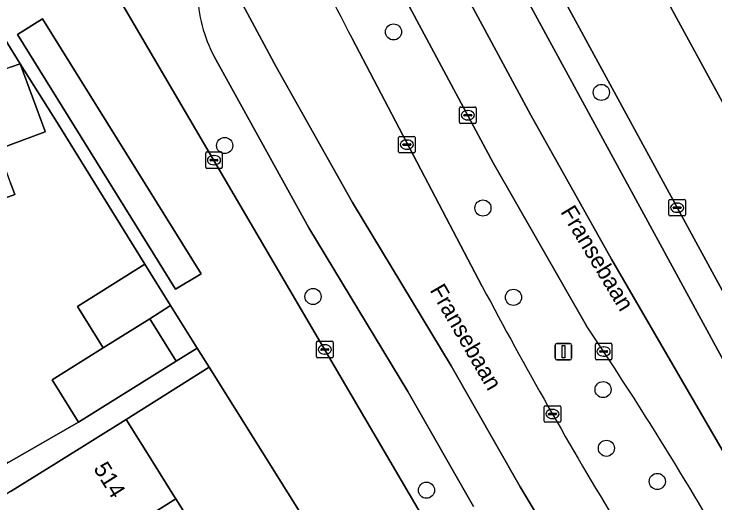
# Model space of a CAD drawing. Extents: x 157767 to 159172, y 387839 to 389425.
# Drawn here: x 158500.2 to 158542.71, y 388310.69 to 388340.3 of the extents above; entities that cross this region are included whole.
import ezdxf

# ---------------------------------------------------------------- set-up
doc = ezdxf.new("R2010")
doc.units = 0
for name, color, linetype in [('IMGEO_Berm_groen', 7, 'Continuous'), ('IMGEO_Boom', 7, 'Continuous'), ('IMGEO_Erf', 7, 'Continuous'), ('IMGEO_Kolk', 7, 'Continuous'), ('IMGEO_Lichtmast', 7, 'Continuous'), ('IMGEO_Muur', 7, 'Continuous'), ('IMGEO_Openbare_ruimte_label', 7, 'Continuous'), ('IMGEO_Pand', 7, 'Continuous'), ('IMGEO_Pand_nummerreeks', 7, 'Continuous'), ('IMGEO_Parkeervlak_open', 7, 'Continuous'), ('IMGEO_Rijbaan_lokaal_gesloten', 7, 'Continuous'), ('IMGEO_Rijbaan_lokaal_open', 7, 'Continuous'), ('IMGEO_Verkeerseiland_open', 7, 'Continuous'), ('IMGEO_Voetpad_open', 7, 'Continuous')]:
    doc.layers.add(name, color=color, linetype=linetype)

msp = doc.modelspace()

# ---------------------------------------------------------------- linework, layer by layer
at = {"layer": 'IMGEO_Berm_groen'}
for points in [[(158529.258, 388331.294), (158524.031, 388341.037)], [(158520.698, 388338.819), (158528.598, 388323.799)], [(158534.917, 388321.411), (158529.258, 388331.294)]]:
    msp.add_lwpolyline(points, dxfattribs=at)
for centre, radius, start, end in [((158763.078, 388464.134), 272.859, 203.9844, 207.33977), ((158776.555, 388455.267), 280.654, 207.9327, 211.32432), ((158344.877, 388193.312), 229.182, 30.48594, 33.98258)]:
    msp.add_arc(centre, radius, start, end, dxfattribs=at)
at = {"layer": 'IMGEO_Boom'}
for centre in [(158523.215, 388339.218), (158535.816, 388335.554), (158512.977, 388332.335), (158528.635, 388328.551), (158518.336, 388323.19), (158530.487, 388323.141), (158535.921, 388317.554), (158536.123, 388313.998), (158539.208, 388311.991), (158525.212, 388311.457)]:
    msp.add_circle(centre, 0.489, dxfattribs=at)
at = {"layer": 'IMGEO_Erf'}
for points in [[(158477.052, 388309.252), (158478.936, 388310.46), (158481.128, 388307.041), (158480.913, 388306.903), (158483.29, 388302.771), (158483.534, 388302.924), (158482.117, 388305.189), (158485.665, 388307.409), (158489.217, 388309.632), (158490.635, 388307.366), (158492.742, 388308.684), (158491.323, 388310.952), (158495, 388313.253), (158498.378, 388315.367), (158499.798, 388313.098), (158504.118, 388315.572), (158502.511, 388318.15), (158505.612, 388320.092), (158504.046, 388322.595), (158508.134, 388325.154), (158502.814, 388333.732), (158500.583, 388337.29), (158500, 388338.235), (158496.17, 388344.444)], [(158500, 388337.076), (158500.583, 388337.29), (158502.065, 388333.257), (158502.098, 388333.166), (158499.238, 388332.119)], [(158500, 388330.073), (158500.244, 388329.371), (158495.536, 388327.648)]]:
    msp.add_lwpolyline(points, dxfattribs=at)
for points in [[(158509.684, 388322.644), (158508.434, 388321.842), (158510.045, 388319.266), (158511.308, 388320.053)], [(158512.028, 388318.905), (158506.997, 388315.751), (158508.597, 388313.194), (158509.89, 388311.127), (158510.015, 388310.928), (158512.878, 388306.351), (158515.743, 388301.774), (158518.606, 388297.197), (158521.472, 388292.617), (158524.478, 388287.813), (158529.553, 388290.95)]]:
    msp.add_lwpolyline(points, close=True, dxfattribs=at)
at = {"layer": 'IMGEO_Kolk'}
for p, q in [((158527.292, 388334.67), (158528.144, 388334.67)), ((158527.217, 388333.744), (158527.217, 388334.596)), ((158527.519, 388334.213), (158527.917, 388334.213)), ((158527.705, 388334.45), (158527.73, 388334.45)), ((158528.218, 388334.596), (158528.218, 388333.744)), ((158527.476, 388334.164), (158527.476, 388334.176)), ((158527.914, 388334.127), (158527.516, 388334.127)), ((158527.728, 388333.89), (158527.703, 388333.89)), ((158527.96, 388334.176), (158527.96, 388334.164)), ((158528.144, 388333.67), (158527.292, 388333.67)), ((158523.526, 388331.964), (158523.526, 388332.816)), ((158523.601, 388332.89), (158524.453, 388332.89)), ((158524.014, 388332.67), (158524.039, 388332.67)), ((158524.527, 388332.816), (158524.527, 388331.964)), ((158523.785, 388332.384), (158523.785, 388332.396)), ((158524.223, 388332.347), (158523.825, 388332.347)), ((158523.828, 388332.433), (158524.226, 388332.433)), ((158524.037, 388332.11), (158524.012, 388332.11)), ((158524.269, 388332.396), (158524.269, 388332.384)), ((158511.826, 388331.025), (158511.826, 388331.877)), ((158511.901, 388331.951), (158512.753, 388331.951)), ((158512.314, 388331.731), (158512.339, 388331.731)), ((158512.827, 388331.877), (158512.827, 388331.025)), ((158524.453, 388331.89), (158523.601, 388331.89)), ((158512.085, 388331.445), (158512.085, 388331.457)), ((158512.523, 388331.408), (158512.125, 388331.408)), ((158512.128, 388331.494), (158512.526, 388331.494)), ((158512.569, 388331.457), (158512.569, 388331.445)), ((158512.753, 388330.951), (158511.901, 388330.951)), ((158512.337, 388331.171), (158512.312, 388331.171)), ((158539.913, 388328.145), (158539.913, 388328.997)), ((158539.988, 388329.071), (158540.84, 388329.071)), ((158540.401, 388328.851), (158540.426, 388328.851)), ((158540.914, 388328.997), (158540.914, 388328.145)), ((158540.172, 388328.565), (158540.172, 388328.577)), ((158540.61, 388328.528), (158540.212, 388328.528)), ((158540.215, 388328.614), (158540.613, 388328.614)), ((158540.424, 388328.291), (158540.399, 388328.291)), ((158540.656, 388328.577), (158540.656, 388328.565)), ((158540.84, 388328.071), (158539.988, 388328.071)), ((158518.546, 388319.559), (158518.546, 388320.411)), ((158518.621, 388320.485), (158519.473, 388320.485)), ((158519.034, 388320.265), (158519.059, 388320.265)), ((158519.547, 388320.411), (158519.547, 388319.559)), ((158535.452, 388319.432), (158535.452, 388320.284)), ((158535.527, 388320.358), (158536.379, 388320.358)), ((158536.453, 388320.284), (158536.453, 388319.432)), ((158518.805, 388319.979), (158518.805, 388319.991)), ((158519.243, 388319.942), (158518.845, 388319.942)), ((158518.848, 388320.028), (158519.246, 388320.028)), ((158519.289, 388319.991), (158519.289, 388319.979)), ((158535.711, 388319.852), (158535.711, 388319.864)), ((158536.149, 388319.815), (158535.751, 388319.815)), ((158535.754, 388319.901), (158536.152, 388319.901)), ((158535.94, 388320.138), (158535.965, 388320.138)), ((158536.195, 388319.864), (158536.195, 388319.852)), ((158519.473, 388319.485), (158518.621, 388319.485)), ((158519.057, 388319.705), (158519.032, 388319.705)), ((158536.379, 388319.358), (158535.527, 388319.358)), ((158535.963, 388319.578), (158535.938, 388319.578)), ((158532.35, 388315.65), (158532.35, 388316.502)), ((158532.425, 388316.576), (158533.277, 388316.576)), ((158532.838, 388316.356), (158532.863, 388316.356)), ((158533.351, 388316.502), (158533.351, 388315.65)), ((158532.609, 388316.07), (158532.609, 388316.082)), ((158533.047, 388316.033), (158532.649, 388316.033)), ((158532.652, 388316.119), (158533.05, 388316.119)), ((158533.093, 388316.082), (158533.093, 388316.07)), ((158533.277, 388315.576), (158532.425, 388315.576)), ((158532.861, 388315.796), (158532.836, 388315.796))]:
    msp.add_line(p, q, dxfattribs=at)
for points in [[(158527.292, 388334.67), (158528.144, 388334.67)], [(158527.217, 388333.744), (158527.217, 388334.596)], [(158528.218, 388334.596), (158528.218, 388333.744)], [(158528.144, 388333.67), (158527.292, 388333.67)], [(158523.526, 388331.964), (158523.526, 388332.816)], [(158523.601, 388332.89), (158524.453, 388332.89)], [(158524.527, 388332.816), (158524.527, 388331.964)], [(158511.826, 388331.025), (158511.826, 388331.877)], [(158511.901, 388331.951), (158512.753, 388331.951)], [(158512.827, 388331.877), (158512.827, 388331.025)], [(158524.453, 388331.89), (158523.601, 388331.89)], [(158512.753, 388330.951), (158511.901, 388330.951)], [(158539.913, 388328.145), (158539.913, 388328.997)], [(158539.988, 388329.071), (158540.84, 388329.071)], [(158540.914, 388328.997), (158540.914, 388328.145)], [(158540.84, 388328.071), (158539.988, 388328.071)], [(158518.546, 388319.559), (158518.546, 388320.411)], [(158518.621, 388320.485), (158519.473, 388320.485)], [(158519.547, 388320.411), (158519.547, 388319.559)], [(158535.452, 388319.432), (158535.452, 388320.284)], [(158535.527, 388320.358), (158536.379, 388320.358)], [(158536.453, 388320.284), (158536.453, 388319.432)], [(158519.473, 388319.485), (158518.621, 388319.485)], [(158536.379, 388319.358), (158535.527, 388319.358)], [(158532.35, 388315.65), (158532.35, 388316.502)], [(158532.425, 388316.576), (158533.277, 388316.576)], [(158533.351, 388316.502), (158533.351, 388315.65)], [(158533.277, 388315.576), (158532.425, 388315.576)]]:
    msp.add_lwpolyline(points, dxfattribs=at)
for centre, radius, start, end in [((158527.294, 388334.594), 0.0765, 91.552, 178.448), ((158527.294, 388334.594), 0.0765, 91.552, 178.448), ((158528.142, 388334.594), 0.0765, 1.552, 88.448), ((158528.142, 388334.594), 0.0765, 1.552, 88.448), ((158527.516, 388334.173), 0.0403, 85.8775, 175.7526), ((158527.921, 388334.175), 0.0386, 1.7309, 96.639), ((158527.513, 388334.163), 0.0366, 178.938, 274.7102), ((158527.917, 388334.17), 0.043, 264.8664, 352.4533), ((158527.294, 388333.746), 0.0765, 181.552, 268.448), ((158527.294, 388333.746), 0.0765, 181.552, 268.448), ((158528.142, 388333.746), 0.0765, 271.552, 358.448), ((158528.142, 388333.746), 0.0765, 271.552, 358.448), ((158523.603, 388332.814), 0.0765, 91.552, 178.448), ((158523.603, 388332.814), 0.0765, 91.552, 178.448), ((158524.451, 388332.814), 0.0765, 1.552, 88.448), ((158524.451, 388332.814), 0.0765, 1.552, 88.448), ((158523.825, 388332.393), 0.0403, 85.8775, 175.7526), ((158523.822, 388332.383), 0.0366, 178.938, 274.7102), ((158524.226, 388332.39), 0.043, 264.8664, 352.4533), ((158524.23, 388332.395), 0.0386, 1.7309, 96.639), ((158511.903, 388331.875), 0.0765, 91.552, 178.448), ((158511.903, 388331.875), 0.0765, 91.552, 178.448), ((158512.751, 388331.875), 0.0765, 1.552, 88.448), ((158512.751, 388331.875), 0.0765, 1.552, 88.448), ((158523.603, 388331.966), 0.0765, 181.552, 268.448), ((158523.603, 388331.966), 0.0765, 181.552, 268.448), ((158524.451, 388331.966), 0.0765, 271.552, 358.448), ((158524.451, 388331.966), 0.0765, 271.552, 358.448), ((158512.125, 388331.454), 0.0403, 85.8775, 175.7526), ((158512.122, 388331.444), 0.0366, 178.938, 274.7102), ((158512.526, 388331.451), 0.043, 264.8664, 352.4533), ((158512.53, 388331.456), 0.0386, 1.7309, 96.639), ((158511.903, 388331.027), 0.0765, 181.552, 268.448), ((158511.903, 388331.027), 0.0765, 181.552, 268.448), ((158512.751, 388331.027), 0.0765, 271.552, 358.448), ((158512.751, 388331.027), 0.0765, 271.552, 358.448), ((158539.99, 388328.995), 0.0765, 91.552, 178.448), ((158539.99, 388328.995), 0.0765, 91.552, 178.448), ((158540.838, 388328.995), 0.0765, 1.552, 88.448), ((158540.838, 388328.995), 0.0765, 1.552, 88.448), ((158540.212, 388328.574), 0.0403, 85.8775, 175.7526), ((158540.209, 388328.564), 0.0366, 178.938, 274.7102), ((158540.613, 388328.571), 0.043, 264.8664, 352.4533), ((158540.617, 388328.576), 0.0386, 1.7309, 96.639), ((158539.99, 388328.147), 0.0765, 181.552, 268.448), ((158539.99, 388328.147), 0.0765, 181.552, 268.448), ((158540.838, 388328.147), 0.0765, 271.552, 358.448), ((158540.838, 388328.147), 0.0765, 271.552, 358.448), ((158518.623, 388320.409), 0.0765, 91.552, 178.448), ((158518.623, 388320.409), 0.0765, 91.552, 178.448), ((158519.471, 388320.409), 0.0765, 1.552, 88.448), ((158519.471, 388320.409), 0.0765, 1.552, 88.448), ((158535.529, 388320.282), 0.0765, 91.552, 178.448), ((158535.529, 388320.282), 0.0765, 91.552, 178.448), ((158536.377, 388320.282), 0.0765, 1.552, 88.448), ((158536.377, 388320.282), 0.0765, 1.552, 88.448), ((158518.845, 388319.988), 0.0403, 85.8775, 175.7526), ((158518.842, 388319.978), 0.0366, 178.938, 274.7102), ((158519.246, 388319.985), 0.043, 264.8664, 352.4533), ((158519.25, 388319.99), 0.0386, 1.7309, 96.639), ((158535.751, 388319.861), 0.0403, 85.8775, 175.7526), ((158535.748, 388319.851), 0.0366, 178.938, 274.7102), ((158536.152, 388319.858), 0.043, 264.8664, 352.4533), ((158536.156, 388319.863), 0.0386, 1.7309, 96.639), ((158518.623, 388319.561), 0.0765, 181.552, 268.448), ((158518.623, 388319.561), 0.0765, 181.552, 268.448), ((158519.471, 388319.561), 0.0765, 271.552, 358.448), ((158519.471, 388319.561), 0.0765, 271.552, 358.448), ((158535.529, 388319.434), 0.0765, 181.552, 268.448), ((158535.529, 388319.434), 0.0765, 181.552, 268.448), ((158536.377, 388319.434), 0.0765, 271.552, 358.448), ((158536.377, 388319.434), 0.0765, 271.552, 358.448), ((158532.427, 388316.5), 0.0765, 91.552, 178.448), ((158532.427, 388316.5), 0.0765, 91.552, 178.448), ((158533.275, 388316.5), 0.0765, 1.552, 88.448), ((158533.275, 388316.5), 0.0765, 1.552, 88.448), ((158532.649, 388316.079), 0.0403, 85.8775, 175.7526), ((158532.646, 388316.069), 0.0366, 178.938, 274.7102), ((158533.05, 388316.076), 0.043, 264.8664, 352.4533), ((158533.054, 388316.081), 0.0386, 1.7309, 96.639), ((158532.427, 388315.652), 0.0765, 181.552, 268.448), ((158532.427, 388315.652), 0.0765, 181.552, 268.448), ((158533.275, 388315.652), 0.0765, 271.552, 358.448), ((158533.275, 388315.652), 0.0765, 271.552, 358.448)]:
    msp.add_arc(centre, radius, start, end, dxfattribs=at)
for centre, major_axis, ratio, start_param, end_param in [((158527.704, 388334.17), (-0.387, 0.002), 0.722429, 4.712389, 7.853982), ((158527.729, 388334.17), (-0.39, 0.002), 0.717154, 1.570796, 4.712389), ((158524.013, 388332.39), (-0.387, 0.002), 0.722429, 4.712389, 7.853982), ((158524.038, 388332.39), (-0.39, 0.002), 0.717154, 1.570796, 4.712389), ((158512.313, 388331.451), (-0.387, 0.002), 0.722429, 4.712389, 7.853982), ((158512.338, 388331.451), (-0.39, 0.002), 0.717154, 1.570796, 4.712389), ((158540.4, 388328.571), (-0.387, 0.002), 0.722429, 4.712389, 7.853982), ((158540.425, 388328.571), (-0.39, 0.002), 0.717154, 1.570796, 4.712389), ((158519.033, 388319.985), (-0.387, 0.002), 0.722429, 4.712389, 7.853982), ((158519.058, 388319.985), (-0.39, 0.002), 0.717154, 1.570796, 4.712389), ((158535.939, 388319.858), (-0.387, 0.002), 0.722429, 4.712389, 7.853982), ((158535.964, 388319.858), (-0.39, 0.002), 0.717154, 1.570796, 4.712389), ((158532.837, 388316.076), (-0.387, 0.002), 0.722429, 4.712389, 7.853982), ((158532.862, 388316.076), (-0.39, 0.002), 0.717154, 1.570796, 4.712389)]:
    msp.add_ellipse(centre, major_axis=major_axis, ratio=ratio, start_param=start_param, end_param=end_param, dxfattribs=at)
at = {"layer": 'IMGEO_Lichtmast'}
for p, q in [((158533.023, 388319.452), (158533.023, 388320.252)), ((158533.023, 388320.252), (158533.023, 388319.452)), ((158533.123, 388320.352), (158533.913, 388320.352)), ((158533.913, 388320.352), (158533.123, 388320.352)), ((158534.013, 388320.252), (158534.013, 388319.452)), ((158534.013, 388319.452), (158534.013, 388320.252)), ((158533.913, 388319.352), (158533.123, 388319.352)), ((158533.123, 388319.352), (158533.913, 388319.352))]:
    msp.add_line(p, q, dxfattribs=at)
msp.add_lwpolyline([(158533.443, 388320.227), (158533.593, 388320.227), (158533.593, 388319.477), (158533.443, 388319.477), (158533.443, 388320.227)], dxfattribs=at)
for centre, start, end in [((158533.123, 388320.252), 90, 180), ((158533.123, 388320.252), 90, 180), ((158533.913, 388320.252), 0, 90), ((158533.913, 388320.252), 360, 90), ((158533.123, 388319.452), 180, 270), ((158533.123, 388319.452), 180, 270), ((158533.913, 388319.452), 270, 0), ((158533.913, 388319.452), 270, 0)]:
    msp.add_arc(centre, 0.1, start, end, dxfattribs=at)
at = {"layer": 'IMGEO_Muur'}
msp.add_lwpolyline([(158502.814, 388333.732), (158508.134, 388325.154)], dxfattribs=at)
at = {"layer": 'IMGEO_Pand'}
for points in [[(158500.583, 388337.29), (158500, 388337.076), (158498.168, 388336.403), (158496.589, 388340.702), (158491.449, 388338.814), (158495.283, 388328.34), (158495.536, 388327.648), (158500.244, 388329.371), (158500, 388330.073), (158499.238, 388332.119), (158502.098, 388333.166), (158502.065, 388333.257)], [(158509.684, 388322.644), (158508.134, 388325.154), (158504.046, 388322.595), (158505.612, 388320.092), (158508.434, 388321.842)], [(158505.612, 388320.092), (158502.511, 388318.15), (158504.118, 388315.572), (158510.045, 388319.266), (158508.434, 388321.842)], [(158510.015, 388310.928), (158509.89, 388311.127), (158508.597, 388313.194), (158506.997, 388315.751), (158502.759, 388313.099), (158500, 388311.373), (158496.927, 388309.45), (158499.952, 388304.616)], [(158512.878, 388306.351), (158510.015, 388310.928), (158499.952, 388304.616), (158502.773, 388300.109), (158502.82, 388300.034), (158505.53, 388301.73)]]:
    msp.add_lwpolyline(points, close=True, dxfattribs=at)
at = {"layer": 'IMGEO_Parkeervlak_open'}
for points in [[(158535.936, 388303.26), (158530.891, 388311.658), (158526.706, 388318.987), (158520.719, 388328.892), (158516.097, 388337.104), (158510.149, 388348.16)], [(158512.335, 388337.725), (158518.083, 388327.354), (158524.075, 388317.441), (158528.055, 388310.472)]]:
    msp.add_lwpolyline(points, dxfattribs=at)
msp.add_lwpolyline([(158510.005, 388323.64), (158511.546, 388324.569), (158501.926, 388340.01), (158500.409, 388339.055)], close=True, dxfattribs=at)
msp.add_arc((158520.322, 388341.877), 9.002, 181.8869, 207.4686, dxfattribs=at)
at = {"layer": 'IMGEO_Rijbaan_lokaal_gesloten'}
for points in [[(158522.774, 388356.867), (158520.193, 388355.786), (158524.893, 388346.524), (158527.752, 388341.202), (158531.535, 388334.178), (158536.428, 388325.454), (158544.459, 388311.65), (158555.339, 388288.902)], [(158556.51, 388294.945), (158522.774, 388356.867)], [(158542.376, 388309.582), (158543.994, 388306.988), (158548.892, 388299.222), (158550.013, 388297.421), (158555.339, 388288.902), (158544.459, 388311.65), (158536.428, 388325.454), (158531.535, 388334.178), (158527.752, 388341.202), (158524.893, 388346.524), (158520.193, 388355.786)], [(158513.779, 388353.22), (158508.675, 388351.089), (158510.149, 388348.16), (158516.097, 388337.104), (158520.719, 388328.892), (158526.706, 388318.987), (158530.891, 388311.658), (158535.936, 388303.26), (158537.124, 388300.9), (158538.816, 388298.433), (158540.051, 388296.6), (158543.772, 388291.077), (158548.944, 388283.404), (158561.929, 388262.53), (158562.62, 388261.425), (158565.51, 388263.197), (158564.255, 388265.206)], [(158524.031, 388341.037), (158529.258, 388331.294), (158534.917, 388321.411)], [(158528.598, 388323.799), (158520.698, 388338.819)]]:
    msp.add_lwpolyline(points, dxfattribs=at)
for centre, radius, start, end in [((158763.078, 388464.134), 272.859, 203.9844, 207.33977), ((158776.555, 388455.267), 280.654, 207.9327, 211.32432), ((158344.877, 388193.312), 229.182, 30.48594, 33.98258)]:
    msp.add_arc(centre, radius, start, end, dxfattribs=at)
at = {"layer": 'IMGEO_Rijbaan_lokaal_open'}
for points in [[(158518.655, 388370.393), (158520.43, 388366.419), (158522.65, 388361.659), (158524.616, 388357.602), (158544.005, 388321.982), (158558.222, 388295.881)], [(158565.72, 388294.121), (158561.354, 388301.588), (158544.005, 388333.408), (158530.905, 388357.407)]]:
    msp.add_lwpolyline(points, dxfattribs=at)
for points in [[(158502.602, 388348.033), (158500, 388352.471), (158496.033, 388353.971), (158495.329, 388353.686), (158492.289, 388352.456), (158496.17, 388344.444), (158500, 388338.235), (158500.583, 388337.29), (158502.814, 388333.732), (158508.134, 388325.154), (158509.684, 388322.644), (158511.308, 388320.053), (158512.028, 388318.905), (158529.553, 388290.95), (158531.97, 388287.052), (158535.956, 388289.514), (158536.64, 388289.939), (158532.05, 388297.782), (158526.372, 388307.483)], [(158510.005, 388323.64), (158500.409, 388339.055), (158501.926, 388340.01), (158511.546, 388324.569)]]:
    msp.add_lwpolyline(points, close=True, dxfattribs=at)
at = {"layer": 'IMGEO_Verkeerseiland_open'}
msp.add_lwpolyline([(158558.222, 388295.881), (158544.005, 388321.982), (158524.616, 388357.602), (158522.774, 388356.867), (158556.51, 388294.945)], dxfattribs=at)
at = {"layer": 'IMGEO_Voetpad_open'}
for points in [[(158530.905, 388357.407), (158544.005, 388333.408), (158561.354, 388301.588), (158565.72, 388294.121)], [(158502.602, 388348.033), (158526.372, 388307.483), (158532.05, 388297.782)], [(158528.055, 388310.472), (158524.075, 388317.441), (158518.083, 388327.354), (158512.335, 388337.725)], [(158500, 388311.373), (158502.759, 388313.099), (158506.997, 388315.751), (158512.028, 388318.905), (158511.308, 388320.053), (158510.045, 388319.266), (158504.118, 388315.572), (158499.798, 388313.098)]]:
    msp.add_lwpolyline(points, dxfattribs=at)
msp.add_arc((158520.322, 388341.877), 9.002, 181.8869, 207.4686, dxfattribs=at)

# ---------------------------------------------------------------- texts
at = {"layer": 'IMGEO_Openbare_ruimte_label'}
for rotation, p in [(301.0522, (158533.307, 388328.322)), (300.1286, (158525.39, 388323.582))]:
    msp.add_text('Fransebaan', height=1, rotation=rotation, dxfattribs=at).set_placement(p)
at = {"layer": 'IMGEO_Pand_nummerreeks'}
msp.add_text('514', height=1, rotation=302.0345, dxfattribs=at).set_placement((158504.99, 388312.775))

doc.saveas('drawing.dxf')
